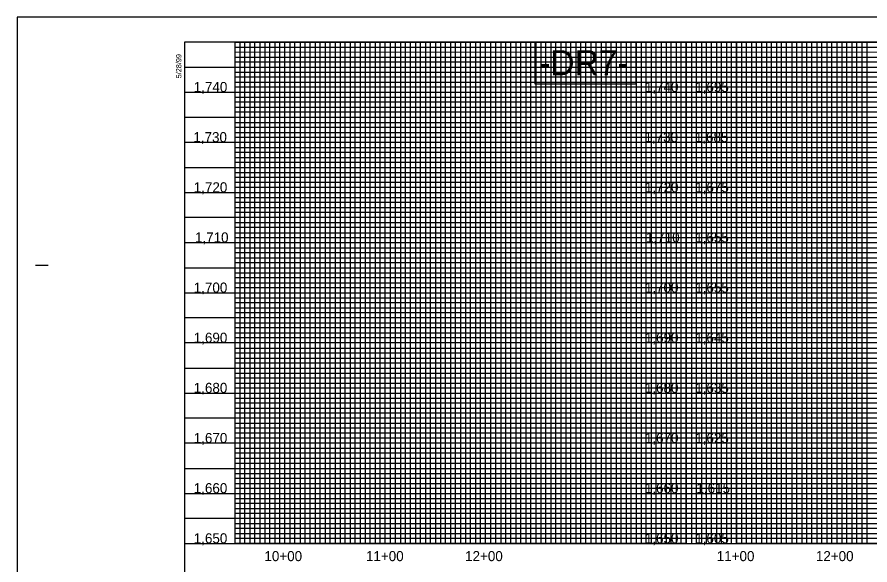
# Model space of a CAD drawing. Extents: x 505602 to 507286, y 483109 to 484209.
# Drawn here: x 505602 to 506452, y 483662 to 484209 of the extents above; entities that cross this region are included whole.
import ezdxf

# ---------------------------------------------------------------- set-up
doc = ezdxf.new("R2010")
doc.units = 0
for name, color, linetype in [('Exist Vertical Profile Vertical Axis Label', 7, 'Continuous'), ('Old_Level_1', 7, 'Continuous'), ('Prop Grid Mask', 7, 'Continuous'), ('Sheet Layout Profile Border Port 1', 7, 'Continuous'), ('Sheet Layout Profile Border Port 2', 7, 'Continuous'), ('Sheet Plot Border Outside CELL', 7, 'Continuous'), ('Sheet Profile CELL', 7, 'Continuous'), ('Sheet Profile Grid Major CELL', 7, 'Continuous'), ('Sheet Profile Grid Middle CELL', 7, 'Continuous'), ('Sheet Profile Grid Minor CELL', 7, 'Continuous')]:
    doc.layers.add(name, color=color, linetype=linetype)

msp = doc.modelspace()

# ---------------------------------------------------------------- linework, layer by layer
at = {"layer": 'Prop Grid Mask'}
msp.add_lwpolyline([(506219.08, 484183.71), (506118.09, 484183.71), (506118.09, 484142), (506219.08, 484142)], close=True, dxfattribs=at)
at = {"layer": 'Sheet Layout Profile Border Port 1'}
msp.add_lwpolyline([(505819.48, 484183.71), (506269.08, 484183.71), (506269.08, 483683.71), (505819.48, 483683.71)], close=True, dxfattribs=at)
at = {"layer": 'Sheet Layout Profile Border Port 2'}
msp.add_lwpolyline([(506319.08, 484183.71), (506694.08, 484183.71), (506694.08, 483683.71), (506319.08, 483683.71)], close=True, dxfattribs=at)
at = {"layer": 'Sheet Plot Border Outside CELL'}
msp.add_lwpolyline([(505602.08, 483108.71), (507286.08, 483108.71), (507286.08, 484208.71), (505602.08, 484208.71)], close=True, dxfattribs=at)
at = {"layer": 'Sheet Profile CELL'}
for p, q in [((506269.08, 483683.71), (506269.08, 484183.71)), ((505620.58, 483961.21), (505633.08, 483961.21)), ((505769.08, 483683.71), (507269.08, 483683.71))]:
    msp.add_line(p, q, dxfattribs=at)
msp.add_lwpolyline([(507269.08, 484183.71), (505769.08, 484183.71), (505769.08, 483133.71), (507269.08, 483133.71)], close=True, dxfattribs=at)
at = {"layer": 'Sheet Profile Grid Major CELL'}
for points in [[(505819.08, 484183.71), (505819.08, 483683.71), (505869.08, 483683.71), (505869.08, 484183.71), (505919.08, 484183.71), (505919.08, 483683.71), (505969.08, 483683.71), (505969.08, 484183.71), (506019.08, 484183.71), (506019.08, 483683.71), (506069.08, 483683.71), (506069.08, 484183.71), (506119.08, 484183.71), (506119.08, 483683.71), (506169.08, 483683.71), (506169.08, 484183.71), (506219.08, 484183.71), (506219.08, 483683.71), (506269.08, 483683.71), (506269.08, 484183.71), (506319.08, 484183.71), (506319.08, 483683.71), (506369.08, 483683.71), (506369.08, 484183.71), (506419.08, 484183.71), (506419.08, 483683.71), (506469.08, 483683.71)], [(505769.08, 484133.71), (507069.08, 484133.71)], [(507069.08, 484083.71), (505769.08, 484083.71), (505769.08, 484033.71), (507069.08, 484033.71)], [(507269.08, 483983.71), (505769.08, 483983.71), (505769.08, 483933.71), (507269.08, 483933.71)], [(507269.08, 483883.71), (505769.08, 483883.71), (505769.08, 483833.71), (507269.08, 483833.71)], [(507269.08, 483783.71), (505769.08, 483783.71), (505769.08, 483783.71), (505769.08, 483733.71), (507269.08, 483733.71)]]:
    msp.add_lwpolyline(points, dxfattribs=at)
at = {"layer": 'Sheet Profile Grid Middle CELL'}
msp.add_line((505769.08, 484158.71), (507069.03, 484158.71), dxfattribs=at)
msp.add_line((505769.08, 484158.71), (507069.03, 484158.71), dxfattribs=at)
for points in [[(505844.08, 484183.71), (505844.08, 483683.71), (505894.08, 483683.71), (505894.08, 484183.71), (505944.08, 484183.71), (505944.08, 483683.71), (505994.08, 483683.71), (505994.08, 484183.71), (506044.08, 484183.71), (506044.08, 483683.71), (506094.08, 483683.71), (506094.08, 484183.71), (506144.08, 484183.71), (506144.08, 483683.71), (506194.08, 483683.71), (506194.08, 484183.71), (506244.08, 484183.71), (506244.08, 483683.71), (506294.08, 483683.71), (506294.08, 484183.71), (506344.08, 484183.71), (506344.08, 483683.71), (506394.08, 483683.71), (506394.08, 483683.71), (506394.08, 484183.71), (506444.08, 484183.71), (506444.08, 483683.71), (506494.08, 483683.71)], [(507069.08, 484108.71), (505769.08, 484108.71), (505769.08, 484058.71), (507069.08, 484058.71)], [(507269.08, 484008.71), (505769.08, 484008.71), (505769.08, 483958.71), (507094.08, 483958.71)], [(507269.08, 483908.71), (505769.08, 483908.71), (505769.08, 483858.71), (507269.08, 483858.71)], [(507269.08, 483808.71), (505769.08, 483808.71), (505769.08, 483758.71), (507269.08, 483758.71)], [(507269.08, 483708.71), (505769.08, 483708.71)]]:
    msp.add_lwpolyline(points, dxfattribs=at)
at = {"layer": 'Sheet Profile Grid Minor CELL'}
for p, q in [((505819.08, 484178.71), (507069.08, 484178.71)), ((505819.08, 484173.71), (505819.08, 484173.71)), ((507069.08, 484173.71), (505819.08, 484173.36)), ((505819.08, 484168.71), (507069.08, 484168.71)), ((507069.03, 484048.71), (505819.08, 484048.71)), ((507069.08, 484043.71), (505819.08, 484043.71)), ((507069.08, 484038.71), (505819.08, 484038.71)), ((505819.08, 484028.71), (507069.08, 484028.71)), ((507069.08, 484023.71), (505819.08, 484023.71)), ((505819.08, 484018.71), (507219.08, 484018.71)), ((507219.08, 483998.71), (505819.08, 483998.71)), ((505819.08, 483993.71), (507219.08, 483993.71)), ((507219.08, 483973.71), (505819.08, 483973.71)), ((505819.08, 483968.71), (507219.08, 483968.71)), ((507219.08, 483948.71), (505819.08, 483948.71)), ((505819.08, 483943.71), (507219.08, 483943.71)), ((507219.08, 483938.71), (505819.08, 483938.71)), ((505819.08, 483928.71), (507219.08, 483928.71)), ((507219.08, 483923.71), (505819.08, 483923.71)), ((505819.08, 483918.71), (507219.08, 483918.71)), ((507219.08, 483913.71), (505819.08, 483913.71)), ((505819.08, 483903.71), (507219.08, 483903.71)), ((507219.08, 483898.71), (505819.08, 483898.71)), ((505819.08, 483893.71), (507219.08, 483893.71)), ((507219.08, 483888.71), (505819.08, 483888.71)), ((505819.08, 483878.71), (507219.08, 483878.71)), ((507219.08, 483873.71), (505819.08, 483873.71)), ((505819.08, 483868.71), (507219.08, 483868.71)), ((507219.08, 483863.71), (505819.08, 483863.71)), ((505819.08, 483853.71), (507219.08, 483853.71)), ((507219.08, 483848.71), (505819.08, 483848.71)), ((505819.08, 483843.71), (507219.08, 483843.71)), ((507219.08, 483838.71), (505819.08, 483838.71)), ((505819.08, 483828.71), (507219.08, 483828.71)), ((507219.08, 483823.71), (505819.08, 483823.71)), ((505819.08, 483818.71), (507219.08, 483818.71)), ((507219.08, 483813.71), (505819.08, 483813.71)), ((505819.08, 483803.71), (507219.08, 483803.71)), ((507219.08, 483798.71), (505819.08, 483798.71)), ((507219.08, 483793.71), (505819.08, 483793.71)), ((507219.08, 483788.71), (505819.08, 483788.71)), ((505819.08, 483778.71), (507219.08, 483778.71)), ((507219.08, 483773.71), (505819.08, 483773.71)), ((505819.08, 483768.71), (507219.08, 483768.71)), ((507219.08, 483763.71), (505819.08, 483763.71)), ((505819.08, 483753.71), (507219.08, 483753.71)), ((507219.08, 483748.71), (505819.08, 483748.71)), ((505819.08, 483743.71), (507219.08, 483743.71)), ((507219.08, 483738.71), (505819.08, 483738.71)), ((505819.08, 483728.71), (507219.08, 483728.71)), ((507219.08, 483723.71), (505819.08, 483723.71)), ((505819.08, 483718.71), (507219.08, 483718.71)), ((507219.08, 483713.71), (505819.08, 483713.71)), ((505819.08, 483703.71), (507219.08, 483703.71)), ((507219.08, 483698.71), (505819.08, 483698.71)), ((505819.08, 483693.71), (507219.08, 483693.71))]:
    msp.add_line(p, q, dxfattribs=at)
for points in [[(505824.08, 484183.71), (505824.08, 483683.71), (505829.08, 483683.71), (505829.08, 484183.71), (505834.08, 484183.71), (505834.08, 483683.71), (505839.08, 483683.71), (505839.08, 484183.71), (505849.08, 484183.71), (505849.08, 483683.71), (505854.08, 483683.71), (505854.08, 484183.71), (505859.08, 484183.71), (505859.08, 483683.71), (505864.08, 483683.71), (505874.08, 483683.71), (505879.08, 483683.71), (505879.08, 484183.71), (505884.08, 484183.71), (505884.08, 483683.71), (505889.08, 483683.71), (505889.08, 484183.71), (505899.08, 484183.71), (505899.08, 483683.71), (505904.08, 483683.71), (505904.08, 484183.71), (505909.08, 484183.71), (505909.08, 483683.71), (505914.08, 483683.71), (505914.08, 484183.71), (505924.08, 484183.71), (505924.08, 483683.71), (505929.08, 483683.71), (505929.08, 484183.71), (505934.08, 484183.71), (505934.08, 483683.71), (505939.08, 483683.71), (505939.08, 484183.71), (505949.08, 484183.71), (505949.08, 483683.71), (505954.08, 483683.71), (505954.08, 484183.71), (505959.08, 484183.71), (505959.08, 483683.71), (505964.08, 483683.71), (505964.08, 484183.71), (505974.08, 484183.71), (505974.08, 483683.71), (505979.08, 483683.71), (505979.08, 484183.71), (505984.08, 484183.71), (505984.08, 483683.71), (505989.08, 483683.71), (505989.08, 484183.71), (505999.08, 484183.71), (505999.08, 483683.71), (506004.08, 483683.71), (506004.08, 484183.71), (506009.08, 484183.71), (506009.08, 483683.71), (506014.08, 483683.71), (506014.08, 484183.71), (506024.08, 484183.71), (506024.08, 483683.71), (506029.08, 483683.71), (506029.08, 484183.71), (506034.08, 484183.71), (506034.08, 483683.71)], [(505864.08, 483683.71), (505864.08, 484183.71), (505874.08, 484183.71), (505874.08, 483683.71)], [(506034.08, 483683.71), (506039.08, 483683.71), (506039.08, 484183.71), (506049.08, 484183.71), (506049.08, 483683.71), (506054.08, 483683.71), (506054.08, 484183.71), (506059.08, 484183.71), (506059.08, 483683.71), (506064.08, 483683.71), (506064.08, 484183.71), (506074.08, 484183.71), (506074.08, 483683.71), (506079.08, 483683.71), (506079.08, 484183.71), (506084.08, 484183.71), (506084.08, 483683.71), (506089.08, 483683.71), (506089.08, 484183.71), (506099.08, 484183.71), (506099.08, 483683.71), (506104.08, 483683.71), (506104.08, 484183.71), (506109.08, 484183.71), (506109.08, 483683.71), (506114.08, 483683.71), (506114.08, 484183.71), (506124.08, 484183.71), (506124.08, 483683.71), (506129.08, 483683.71), (506129.08, 484183.71), (506134.08, 484183.71), (506134.08, 483683.71), (506139.08, 483683.71), (506139.08, 484183.71), (506149.08, 484183.71), (506149.08, 483683.71), (506154.08, 483683.71), (506154.08, 484183.71), (506159.08, 484183.71), (506159.08, 483683.71), (506164.08, 483683.71), (506164.08, 484183.71), (506174.08, 484183.71), (506174.08, 483683.71), (506179.08, 483683.71), (506179.08, 484183.71), (506184.08, 484183.71), (506184.08, 483683.71), (506189.08, 483683.71), (506189.08, 484183.71), (506199.08, 484183.71), (506199.08, 483683.71), (506204.08, 483683.71), (506204.08, 484183.71), (506209.08, 484183.71), (506209.08, 483683.71), (506214.08, 483683.71), (506214.08, 484183.71), (506224.08, 484183.71), (506224.08, 483683.71), (506229.08, 483683.71), (506229.08, 484183.71), (506234.08, 484183.71), (506234.08, 483683.71), (506239.08, 483683.71), (506239.08, 484183.71), (506249.08, 484183.71), (506249.08, 483683.71), (506254.08, 483683.71), (506254.08, 484183.71), (506259.08, 484183.71), (506259.08, 483683.71), (506264.08, 483683.71), (506264.08, 484183.71), (506274.08, 484183.71), (506274.08, 483683.71), (506279.08, 483683.71), (506279.08, 484183.71), (506284.08, 484183.71), (506284.08, 483683.71), (506289.08, 483683.71), (506289.08, 484183.71), (506299.08, 484183.71), (506299.08, 483683.71), (506304.08, 483683.71), (506304.08, 484183.71), (506309.08, 484183.71), (506309.08, 483683.71), (506314.08, 483683.71), (506314.08, 484183.71), (506324.08, 484183.71), (506324.08, 483683.71), (506329.08, 483683.71), (506329.08, 484183.71), (506334.08, 484183.71), (506334.08, 483683.71), (506339.08, 483683.71), (506339.08, 484183.71), (506349.08, 484183.71)], [(506349.08, 484183.71), (506349.08, 483683.71), (506354.08, 483683.71), (506354.08, 484183.71), (506359.08, 484183.71), (506359.08, 483683.71), (506364.08, 483683.71), (506364.08, 484183.71), (506374.08, 484183.71), (506374.08, 483683.71), (506379.08, 483683.71), (506379.08, 484183.71), (506384.08, 484183.71), (506384.08, 483683.71), (506389.08, 483683.71), (506389.08, 484183.71), (506399.08, 484183.71), (506399.08, 483683.71), (506404.08, 483683.71), (506404.08, 484183.71), (506409.08, 484183.71), (506409.08, 483683.71), (506414.08, 483683.71), (506414.08, 484183.71), (506424.08, 484183.71), (506424.08, 483683.71), (506429.08, 483683.71), (506429.08, 484183.71), (506434.08, 484183.71), (506434.08, 483683.71), (506439.08, 483683.71), (506439.08, 484183.71), (506449.08, 484183.71), (506449.08, 483683.71), (506454.08, 483683.71)], [(507069.08, 484163.71), (505819.08, 484163.71), (505819.08, 484153.71), (507069.08, 484153.71)], [(507069.03, 484148.71), (505819.08, 484148.71), (505819.08, 484143.71), (507069.08, 484143.71)], [(507069.08, 484138.71), (505819.08, 484138.71), (505819.08, 484128.71), (507069.08, 484128.71)], [(507069.08, 484123.71), (505819.08, 484123.71), (505819.08, 484118.71), (507069.08, 484118.71)], [(507069.08, 484113.71), (505819.08, 484113.71), (505819.08, 484103.71), (507069.08, 484103.71)], [(507069.08, 484098.71), (505819.08, 484098.71), (505819.08, 484093.71), (507069.08, 484093.71)], [(507069.08, 484088.71), (505819.08, 484088.71), (505819.08, 484078.71), (507069.08, 484078.71)], [(507069.08, 484073.61), (505819.18, 484073.61), (505819.18, 484068.71), (507069.08, 484068.71)], [(507069.08, 484063.71), (505819.08, 484063.71), (505819.08, 484053.71), (507069.08, 484053.71)], [(507219.08, 484013.71), (505819.08, 484013.71), (505819.08, 484003.71), (507219.08, 484003.71)], [(507219.08, 483988.71), (505819.08, 483988.71), (505819.08, 483978.71), (507219.08, 483978.71)], [(507219.08, 483963.71), (505819.08, 483963.71), (505819.08, 483953.71), (507219.08, 483953.71)], [(507219.08, 483688.71), (505819.08, 483688.71)]]:
    msp.add_lwpolyline(points, dxfattribs=at)

# ---------------------------------------------------------------- texts
at = {"layer": 'Exist Vertical Profile Vertical Axis Label'}
for s, p in [('1,740', (505778.18, 484133.96)), ('1,740', (506227.78, 484133.96)), ('1,695', (506277.98, 484133.96)), ('1,730', (505777.78, 484083.96)), ('1,730', (506227.38, 484083.96)), ('1,685', (506277.58, 484083.96)), ('1,720', (505778.18, 484033.96)), ('1,720', (506227.78, 484033.96)), ('1,675', (506277.98, 484033.96)), ('1,710', (505779.38, 483983.96)), ('1,710', (506228.97, 483983.96)), ('1,655', (506277.98, 483983.96)), ('1,700', (505778.18, 483933.96)), ('1,700', (506227.78, 483933.96)), ('1,655', (506277.98, 483933.96)), ('1,690', (505778.18, 483883.96)), ('1,690', (506227.78, 483883.96)), ('1,690', (506227.78, 483883.96)), ('1,690', (506227.78, 483883.96)), ('1,690', (506227.78, 483883.96)), ('1,645', (506277.98, 483883.96)), ('1,680', (505778.18, 483833.96)), ('1,680', (506227.78, 483833.96)), ('1,635', (506277.98, 483833.96)), ('1,670', (505778.18, 483783.96)), ('1,670', (506227.78, 483783.96)), ('1,625', (506277.98, 483783.96)), ('1,660', (505778.18, 483733.96)), ('1,660', (506227.78, 483733.96)), ('1,615', (506279.18, 483733.96)), ('1,650', (505778.18, 483683.96)), ('1,650', (506227.78, 483683.96)), ('1,605', (506277.98, 483683.96)), ('10+00', (505848.61, 483666.21)), ('11+00', (505949.81, 483666.21)), ('12+00', (506048.61, 483666.21)), ('11+00', (506299.41, 483666.21)), ('12+00', (506398.21, 483666.21))]:
    msp.add_text(s, height=10, dxfattribs=at).set_placement(p)
at = {"layer": 'Old_Level_1'}
msp.add_text('-DR7-', height=25, dxfattribs=at).set_placement((506122.42, 484150.68))
at = {"layer": 'Sheet Profile CELL'}
msp.add_text('5/28/99', height=5.25, rotation=90, dxfattribs=at).set_placement((505765.84, 484147.62))

doc.saveas('drawing.dxf')
